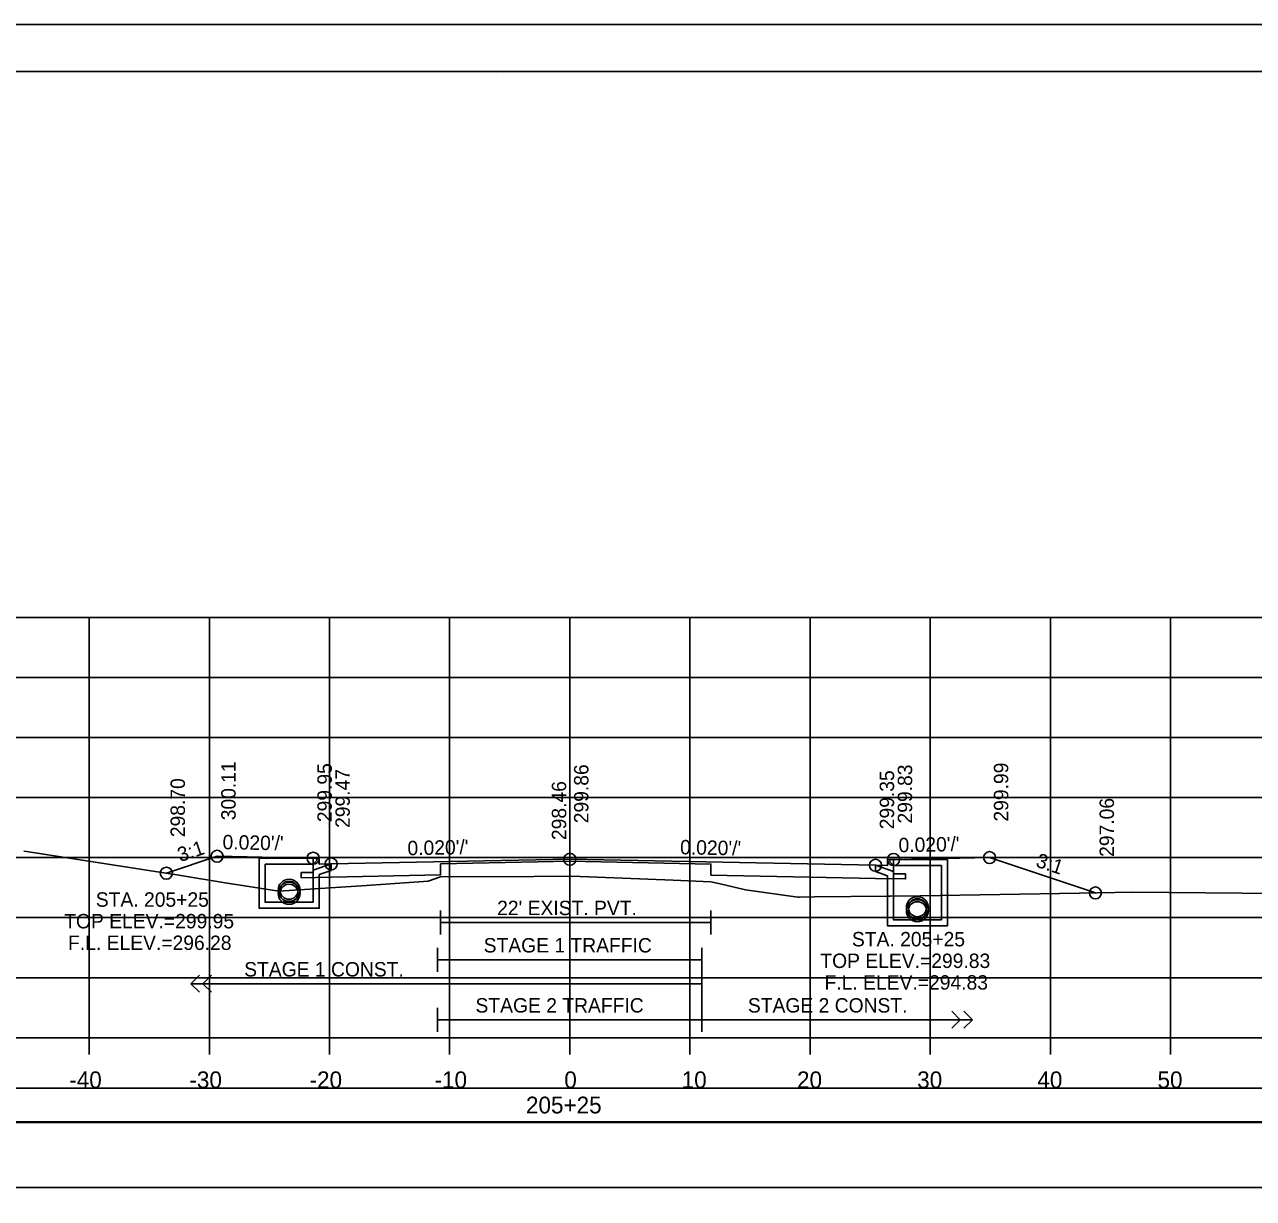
# Model space of a CAD drawing. Extents: x 1368122 to 1710785, y 373130 to 557566.
# Drawn here: x 1369976.9 to 1370079.1, y 374099.3 to 374197 of the extents above; entities that cross this region are included whole.
import ezdxf

# ---------------------------------------------------------------- set-up
doc = ezdxf.new("R2010")
doc.units = 0
for name, color, linetype in [('R_Alt Surface', 7, 'Continuous'), ('R_Axis', 7, 'Continuous'), ('R_Axis Annot', 7, 'Continuous'), ('R_Border', 7, 'Continuous'), ('R_Exist Surface', 7, 'Continuous'), ('R_Fin Surface', 7, 'Continuous'), ('R_Grid', 7, 'Continuous'), ('R_No Plot', 7, 'Continuous'), ('R_Striping', 7, 'Continuous'), ('R_Water', 7, 'Continuous'), ('R_Water Annot', 7, 'Continuous'), ('R_Xsect Elev', 7, 'Continuous'), ('R_Xsect Slope', 7, 'Continuous')]:
    doc.layers.add(name, color=color, linetype=linetype)

msp = doc.modelspace()

# ---------------------------------------------------------------- linework, layer by layer
for points in [[(1369873.09, 374105.65), (1370171.39, 374105.65), (1370171.39, 374108.47), (1369873.09, 374108.47)], [(1369873.09, 374100.19), (1370171.39, 374100.19), (1370171.39, 374105.6), (1369873.09, 374105.6)]]:
    msp.add_lwpolyline(points, close=True)
at = {"layer": 'R_Alt Surface'}
for points in [[(1370049.18, 374127.5), (1370049.18, 374126.32), (1370050.18, 374126.3), (1370050.18, 374125.88), (1370047.68, 374125.93), (1370033.99, 374126.2), (1370033.99, 374127.12), (1370022.24, 374127.35), (1370011.49, 374127.14), (1370011.49, 374126.22), (1370002.38, 374126.04), (1369999.88, 374125.99), (1369999.88, 374126.41), (1370000.88, 374126.43), (1370000.88, 374127.61)], [(1370011.49, 374123.27), (1370011.49, 374121.27)], [(1370033.99, 374123.27), (1370033.99, 374121.27)], [(1370011.49, 374122.27), (1370033.99, 374122.27)]]:
    msp.add_lwpolyline(points, dxfattribs=at)
at = {"layer": 'R_Axis'}
for p, q in [((1369872.24, 374112.66), (1370172.24, 374112.66)), ((1369982.24, 374111.26), (1369982.24, 374112.66)), ((1369992.24, 374111.26), (1369992.24, 374112.66)), ((1370002.24, 374111.26), (1370002.24, 374112.66)), ((1370012.24, 374111.26), (1370012.24, 374112.66)), ((1370022.24, 374111.26), (1370022.24, 374112.66)), ((1370032.24, 374111.26), (1370032.24, 374112.66)), ((1370042.24, 374111.26), (1370042.24, 374112.66)), ((1370052.24, 374111.26), (1370052.24, 374112.66)), ((1370062.24, 374111.26), (1370062.24, 374112.66)), ((1370072.24, 374111.26), (1370072.24, 374112.66))]:
    msp.add_line(p, q, dxfattribs=at)
at = {"layer": 'R_Border'}
for p, q in [((1369864.24, 374193.12), (1370180.42, 374193.12)), ((1370016.76, 374192.86), (1370016.76, 374192.86)), ((1370016.76, 374192.86), (1370016.76, 374192.86))]:
    msp.add_line(p, q, dxfattribs=at)
at = {"layer": 'R_Exist Surface'}
msp.add_lwpolyline([(1369976.8, 374128.21), (1369977.02, 374128.17), (1369989.7, 374126.2), (1369993.55, 374125.56), (1369998.02, 374124.86), (1370005.33, 374125.35), (1370010.44, 374125.69), (1370011.49, 374126.06), (1370019.25, 374126.1), (1370022.42, 374126.12), (1370030.84, 374125.78), (1370033.99, 374125.64), (1370034.75, 374125.49), (1370036.87, 374124.99), (1370041.23, 374124.38), (1370041.28, 374124.38), (1370041.34, 374124.38), (1370042.61, 374124.39), (1370048.63, 374124.45), (1370048.89, 374124.46), (1370051.41, 374124.49), (1370064.65, 374124.7), (1370069.06, 374124.79), (1370081.22, 374124.68)], dxfattribs=at)
at = {"layer": 'R_Fin Surface'}
msp.add_lwpolyline([(1369988.66, 374126.36), (1369992.88, 374127.77), (1369997.88, 374127.67), (1370000.88, 374127.61), (1370001.38, 374127.61), (1370001.38, 374127.11), (1370002.38, 374127.13), (1370022.24, 374127.52), (1370047.68, 374127.02), (1370048.68, 374127), (1370048.68, 374127.5), (1370049.18, 374127.5), (1370052.18, 374127.56), (1370057.18, 374127.66), (1370065.98, 374124.72)], dxfattribs=at)
at = {"layer": 'R_Grid'}
for p, q in [((1369872.24, 374147.66), (1370172.24, 374147.66)), ((1369982.24, 374112.66), (1369982.24, 374147.66)), ((1369992.24, 374112.66), (1369992.24, 374147.66)), ((1370002.24, 374112.66), (1370002.24, 374147.66)), ((1370012.24, 374112.66), (1370012.24, 374147.66)), ((1370022.24, 374112.66), (1370022.24, 374147.66)), ((1370032.24, 374112.66), (1370032.24, 374147.66)), ((1370042.24, 374112.66), (1370042.24, 374147.66)), ((1370052.24, 374112.66), (1370052.24, 374147.66)), ((1370062.24, 374112.66), (1370062.24, 374147.66)), ((1370072.24, 374112.66), (1370072.24, 374147.66)), ((1369872.24, 374142.66), (1370172.24, 374142.66)), ((1369872.24, 374137.66), (1370172.24, 374137.66)), ((1369872.24, 374132.66), (1370172.24, 374132.66)), ((1369872.24, 374127.66), (1370172.24, 374127.66)), ((1369872.24, 374122.66), (1370172.24, 374122.66)), ((1369872.24, 374117.66), (1370172.24, 374117.66)), ((1369872.24, 374112.66), (1370172.24, 374112.66))]:
    msp.add_line(p, q, dxfattribs=at)
at = {"layer": 'R_No Plot'}
msp.add_line((1369851.84, 374197.02), (1370185.17, 374197.02), dxfattribs=at)
for points in [[(1369851.83, 374197.02), (1370185.17, 374197.02), (1370185.17, 373983.68), (1369851.83, 373983.68)], [(1370098.16, 374193.12), (1370117.78, 374193.12), (1370117.78, 374183.24), (1370133.89, 374183.24), (1370157.09, 374183.24), (1370157.21, 374155.08), (1370180.42, 374155.08), (1370180.42, 373987.66), (1369864.24, 373987.66), (1369864.24, 374193.12)]]:
    msp.add_lwpolyline(points, close=True, dxfattribs=at)
for centre, radius in [((1369992.88, 374127.77), 0.5), ((1370000.88, 374127.61), 0.5), ((1370002.38, 374127.13), 0.5), ((1370022.24, 374127.52), 0.5), ((1370047.68, 374127.02), 0.5), ((1370049.18, 374127.5), 0.5), ((1370057.18, 374127.66), 0.5), ((1369988.66, 374126.36), 0.5), ((1369998.88, 374124.94), 0.917), ((1369998.88, 374124.69), 0.917), ((1370065.98, 374124.72), 0.5), ((1370051.17, 374123.49), 0.917), ((1370051.17, 374123.24), 0.917)]:
    msp.add_circle(centre, radius, dxfattribs=at)
at = {"layer": 'R_Striping'}
for p, q in [((1369990.71, 374117.16), (1369991.41, 374117.87)), ((1369991.71, 374117.16), (1369992.41, 374117.87)), ((1369991.41, 374116.45), (1369990.71, 374117.16)), ((1369992.41, 374116.45), (1369991.71, 374117.16)), ((1370054.74, 374114.16), (1370054.04, 374114.87)), ((1370055.74, 374114.16), (1370055.04, 374114.87)), ((1370055.74, 374114.16), (1370033.24, 374114.16)), ((1370054.04, 374113.45), (1370054.74, 374114.16)), ((1370055.04, 374113.45), (1370055.74, 374114.16))]:
    msp.add_line(p, q, dxfattribs=at)
for points in [[(1370011.24, 374120.16), (1370011.24, 374118.16)], [(1370033.24, 374120.16), (1370033.24, 374113.16)], [(1370033.24, 374120.16), (1370033.24, 374118.16)], [(1370011.24, 374119.16), (1370033.24, 374119.16)], [(1370033.24, 374117.16), (1369990.71, 374117.16)], [(1370011.24, 374115.16), (1370011.24, 374113.16)], [(1370011.24, 374114.16), (1370033.24, 374114.16)]]:
    msp.add_lwpolyline(points, dxfattribs=at)
at = {"layer": 'R_Water'}
for p, q in [((1369996.38, 374127.61), (1370001.13, 374127.61)), ((1369996.38, 374126.11), (1369996.38, 374127.61)), ((1370001.21, 374127.44), (1370001.13, 374127.61)), ((1370048.84, 374127.33), (1370048.92, 374127.5)), ((1370053.67, 374127.5), (1370048.92, 374127.5)), ((1370053.67, 374126), (1370053.67, 374127.5)), ((1369996.88, 374126.11), (1369996.88, 374127.11)), ((1369996.88, 374127.11), (1370000.88, 374127.11)), ((1370001.21, 374127.44), (1370000.88, 374127.11)), ((1370002.38, 374127.13), (1370000.88, 374126.61)), ((1370000.88, 374126.11), (1370000.88, 374126.61)), ((1370002.38, 374126.6), (1370001.38, 374126.25)), ((1370047.67, 374127.02), (1370049.17, 374126.5)), ((1370047.67, 374126.49), (1370048.67, 374126.14)), ((1370048.84, 374127.33), (1370049.17, 374127)), ((1370053.17, 374127), (1370049.17, 374127)), ((1370049.17, 374126), (1370049.17, 374126.5)), ((1370053.17, 374126), (1370053.17, 374127)), ((1370001.38, 374126.11), (1370001.38, 374126.25)), ((1370048.67, 374126), (1370048.67, 374126.14))]:
    msp.add_line(p, q, dxfattribs=at)
for points in [[(1370002.38, 374126.6), (1370002.38, 374127.13)], [(1370047.67, 374126.49), (1370047.67, 374127.02)], [(1370001.38, 374126.11), (1370001.38, 374123.44), (1369998.88, 374123.44), (1369996.38, 374123.44), (1369996.38, 374126.11)], [(1370000.88, 374126.11), (1370000.88, 374123.94), (1369998.88, 374123.94), (1369996.88, 374123.94), (1369996.88, 374126.11)], [(1370053.67, 374126), (1370053.67, 374121.99), (1370051.17, 374121.99), (1370048.67, 374121.99), (1370048.67, 374126)], [(1370053.17, 374126), (1370053.17, 374122.49), (1370051.17, 374122.49), (1370049.17, 374122.49), (1370049.17, 374126)]]:
    msp.add_lwpolyline(points, dxfattribs=at)
for centre in [(1369998.88, 374124.94), (1369998.88, 374124.69), (1370051.17, 374123.49), (1370051.17, 374123.24)]:
    msp.add_circle(centre, 0.75, dxfattribs=at)
at = {"layer": 'R_Xsect Elev'}
msp.add_line((1370022.24, 374126.12), (1370022.24, 374136.12), dxfattribs=at)

# ---------------------------------------------------------------- texts
at = {"layer": 'R_Axis Annot'}
for s, p in [('-40', (1369980.58, 374108.46)), ('-30', (1369990.58, 374108.46)), ('-20', (1370000.58, 374108.46)), ('-10', (1370010.98, 374108.46)), ('0', (1370021.78, 374108.46)), ('10', (1370031.55, 374108.46)), ('20', (1370041.15, 374108.46)), ('30', (1370051.15, 374108.46)), ('40', (1370061.15, 374108.46)), ('50', (1370071.15, 374108.46)), ('205+25', (1370018.59, 374106.36))]:
    msp.add_text(s, height=1.4, dxfattribs=at).set_placement(p)
at = {"layer": 'R_Striping'}
for s, p in [('STAGE 1 TRAFFIC', (1370015.07, 374119.76)), ('STAGE 1 CONST.', (1369995.14, 374117.76)), ('STAGE 2 TRAFFIC', (1370014.39, 374114.76)), ('STAGE 2 CONST.', (1370037.06, 374114.76))]:
    msp.add_text(s, height=1.2, dxfattribs=at).set_placement(p)
at = {"layer": 'R_Water'}
msp.add_text("22' EXIST. PVT.", height=1.2, dxfattribs=at).set_placement((1370016.19, 374122.87))
at = {"layer": 'R_Water Annot'}
for s, p in [('STA. 205+25', (1369982.79, 374123.57)), ('TOP ELEV.=299.95', (1369980.16, 374121.77)), ('STA. 205+25', (1370045.72, 374120.27)), ('F.L. ELEV.=296.28', (1369980.48, 374119.97)), ('TOP ELEV.=299.83', (1370043.09, 374118.47)), ('F.L. ELEV.=294.83', (1370043.44, 374116.67))]:
    msp.add_text(s, height=1.2, dxfattribs=at).set_placement(p)
at = {"layer": 'R_Xsect Elev'}
for s, p in [('300.11', (1369994.43, 374130.77)), ('299.95', (1370002.43, 374130.61)), ('299.47', (1370003.93, 374130.13)), ('299.86', (1370023.79, 374130.52)), ('299.35', (1370049.23, 374130.02)), ('299.83', (1370050.73, 374130.5)), ('299.99', (1370058.73, 374130.66)), ('298.70', (1369990.21, 374129.36)), ('298.46', (1370021.94, 374129.12)), ('297.06', (1370067.53, 374127.72))]:
    msp.add_text(s, height=1.2, rotation=90, dxfattribs=at).set_placement(p)
at = {"layer": 'R_Xsect Slope'}
for s, rotation, p in [("0.020'/'", 358.8542, (1369993.33, 374128.36)), ('3:1', 18.4349, (1369989.82, 374127.28)), ("0.020'/'", 1.1458, (1370008.74, 374127.85)), ("0.020'/'", 358.8542, (1370031.41, 374127.94)), ("0.020'/'", 1.1458, (1370049.61, 374128.1)), ('3:1', 341.5651, (1370060.95, 374126.93))]:
    msp.add_text(s, height=1.2, rotation=rotation, dxfattribs=at).set_placement(p)

doc.saveas('drawing.dxf')
